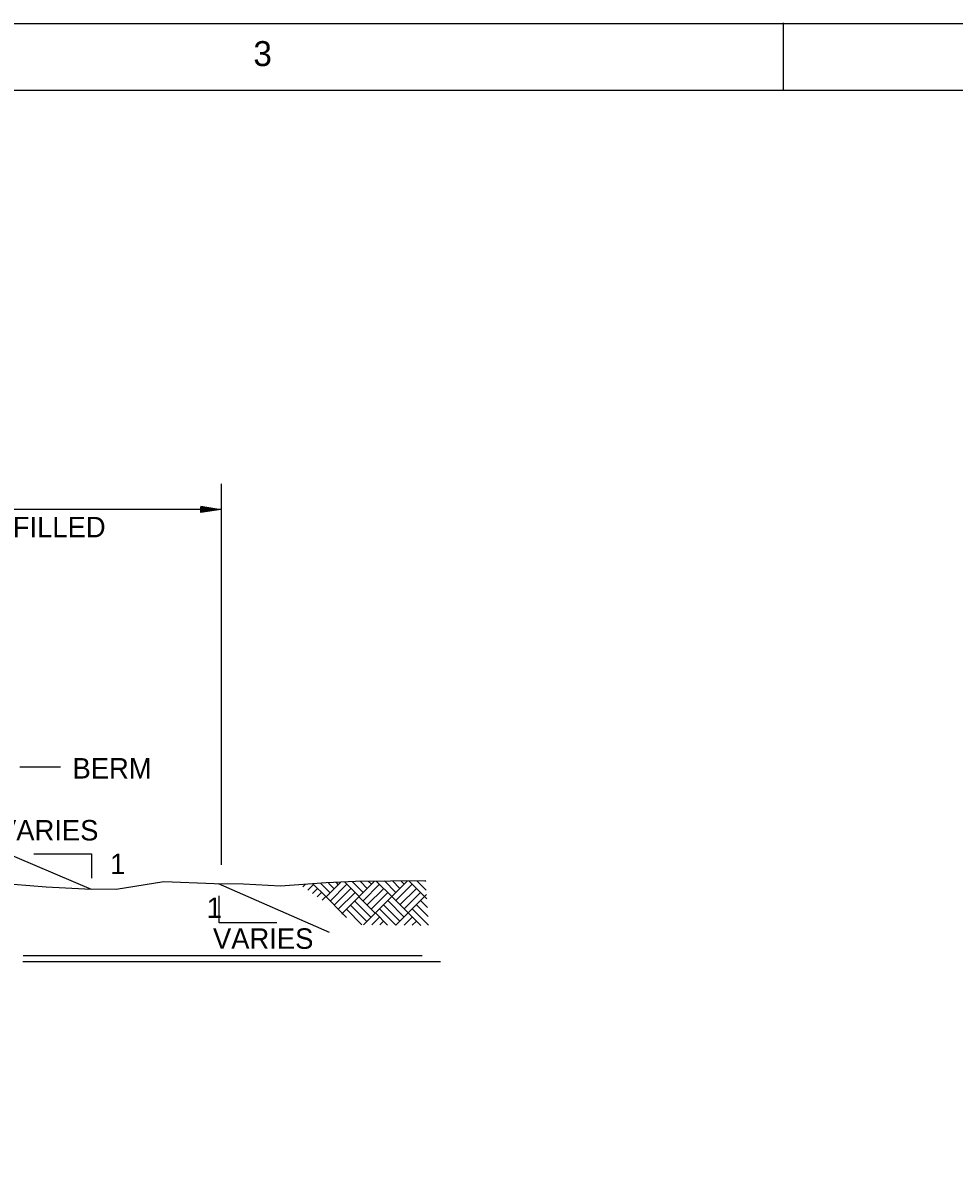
# Model space of a CAD drawing. Extents: x 2127959 to 2137375, y 2146193 to 2153470.
# Drawn here: x 2132094 to 2133592, y 2151626 to 2153470 of the extents above; entities that cross this region are included whole.
import ezdxf

# ---------------------------------------------------------------- set-up
doc = ezdxf.new("R2010")
doc.units = 0
for name, color, linetype in [('Level 1', 7, 'Continuous'), ('Level 3', 7, 'Continuous'), ('Level 5', 7, 'Continuous'), ('Level 50', 7, 'Continuous')]:
    doc.layers.add(name, color=color, linetype=linetype)

msp = doc.modelspace()

# ---------------------------------------------------------------- linework, layer by layer
at = {"layer": 'Level 1'}
for p, q in [((2133317.479, 2153362.032), (2133317.499, 2153469.881)), ((2128280.166, 2153362.032), (2136678.794, 2153362.027)), ((2132154.777, 2152273.049), (2132089.203, 2152273.049)), ((2132055.253, 2152140.601), (2132204.181, 2152077.145)), ((2132055.253, 2152140.601), (2132204.181, 2152077.145)), ((2132055.253, 2152140.601), (2132204.181, 2152077.145)), ((2132408.448, 2152086.019), (2132586.625, 2152008.043)), ((2132408.448, 2152086.019), (2132586.625, 2152008.043)), ((2132408.448, 2152086.019), (2132586.625, 2152008.043))]:
    msp.add_line(p, q, dxfattribs=at)
msp.add_lwpolyline([(2127959.193, 2153469.025), (2137374.681, 2153469.025), (2137374.681, 2146193.484), (2127959.193, 2146193.484)], close=True, dxfattribs=at)
at = {"layer": 'Level 3'}
for p, q in [((2132413.663, 2152116.49), (2132413.663, 2152728.641)), ((2132413.663, 2152687.675), (2131787.674, 2152687.675)), ((2132111.874, 2152134.155), (2132204.383, 2152134.155)), ((2132204.383, 2152134.155), (2132204.383, 2152094.984)), ((2132409.712, 2152023.008), (2132409.712, 2152066.457)), ((2132502.6, 2152023.008), (2132409.712, 2152023.008)), ((2132094.614, 2151970.318), (2132736.266, 2151970.318)), ((2132094.614, 2151970.318), (2132736.266, 2151970.318)), ((2132094.614, 2151970.318), (2132736.266, 2151970.318)), ((2132094.405, 2151961.01), (2132765.709, 2151961.01)), ((2132094.405, 2151961.01), (2132765.709, 2151961.01)), ((2132094.405, 2151961.01), (2132765.709, 2151961.01))]:
    msp.add_line(p, q, dxfattribs=at)
at = {"layer": 'Level 5'}
for p, q in [((2132079.302, 2152085.126), (2132131.876, 2152080.794)), ((2132079.302, 2152085.126), (2132131.876, 2152080.794)), ((2132079.302, 2152085.126), (2132131.876, 2152080.794)), ((2132131.876, 2152080.794), (2132193.754, 2152077.667)), ((2132131.876, 2152080.794), (2132193.754, 2152077.667)), ((2132131.876, 2152080.794), (2132193.754, 2152077.667)), ((2132244.523, 2152077.426), (2132321.132, 2152089.685)), ((2132244.523, 2152077.426), (2132321.132, 2152089.685)), ((2132244.523, 2152077.426), (2132321.132, 2152089.685)), ((2132321.132, 2152089.685), (2132401.941, 2152086.08)), ((2132321.132, 2152089.685), (2132401.941, 2152086.08)), ((2132321.132, 2152089.685), (2132401.941, 2152086.08)), ((2132401.941, 2152086.08), (2132449.091, 2152085.606)), ((2132401.941, 2152086.08), (2132449.091, 2152085.606)), ((2132401.941, 2152086.08), (2132449.091, 2152085.606)), ((2132449.091, 2152085.606), (2132508.573, 2152082.475)), ((2132449.091, 2152085.606), (2132508.573, 2152082.475)), ((2132449.091, 2152085.606), (2132508.573, 2152082.475)), ((2132508.573, 2152082.475), (2132581.873, 2152088.001)), ((2132508.573, 2152082.475), (2132581.873, 2152088.001)), ((2132508.573, 2152082.475), (2132581.873, 2152088.001)), ((2132548.708, 2152085.26), (2132544.628, 2152081.165)), ((2132552.34, 2152075.713), (2132561.548, 2152084.931)), ((2132581.338, 2152065.187), (2132560.683, 2152085.841)), ((2132587.905, 2152071.752), (2132573.208, 2152086.452)), ((2132605.182, 2152088.001), (2132581.86, 2152064.678)), ((2132581.873, 2152088.001), (2132629.337, 2152089.921)), ((2132581.873, 2152088.001), (2132629.337, 2152089.921)), ((2132581.873, 2152088.001), (2132629.337, 2152089.921)), ((2132585.807, 2152087.063), (2132594.489, 2152078.351)), ((2132588.428, 2152058.067), (2132614.774, 2152084.409)), ((2132598.345, 2152087.675), (2132601.07, 2152084.931)), ((2132611.931, 2152088.329), (2132635.042, 2152065.216)), ((2132641.654, 2152071.767), (2132624.467, 2152088.938)), ((2132629.337, 2152089.921), (2132741.988, 2152090.888)), ((2132629.337, 2152089.921), (2132741.988, 2152090.888)), ((2132629.337, 2152089.921), (2132741.988, 2152090.888)), ((2132660.059, 2152090.191), (2132635.087, 2152065.216)), ((2132648.207, 2152078.365), (2132637.035, 2152089.549)), ((2132641.654, 2152058.604), (2132667.999, 2152084.948)), ((2132649.667, 2152090.102), (2132654.821, 2152084.948)), ((2132662.726, 2152090.22), (2132687.732, 2152065.216)), ((2132694.212, 2152071.901), (2132675.803, 2152090.325)), ((2132687.612, 2152065.32), (2132712.946, 2152090.636)), ((2132700.794, 2152078.487), (2132688.834, 2152090.443)), ((2132694.181, 2152058.752), (2132720.538, 2152085.098)), ((2132701.911, 2152090.547), (2132707.39, 2152085.081)), ((2132740.271, 2152065.32), (2132714.912, 2152090.653)), ((2132743.026, 2152075.476), (2132727.75, 2152090.769)), ((2132740.825, 2152090.875), (2132742.074, 2152089.622)), ((2132193.754, 2152077.667), (2132244.523, 2152077.426)), ((2132193.754, 2152077.667), (2132244.523, 2152077.426)), ((2132193.754, 2152077.667), (2132244.523, 2152077.426)), ((2132560.057, 2152070.279), (2132568.127, 2152078.351)), ((2132574.727, 2152071.752), (2132567.786, 2152064.826)), ((2132581.293, 2152065.187), (2132575.485, 2152059.378)), ((2132608.19, 2152038.305), (2132581.86, 2152064.635)), ((2132595.024, 2152051.513), (2132621.355, 2152077.845)), ((2132627.951, 2152071.246), (2132601.594, 2152044.888)), ((2132634.504, 2152064.678), (2132608.19, 2152038.347)), ((2132634.504, 2152064.635), (2132660.731, 2152038.408)), ((2132648.251, 2152052.05), (2132674.567, 2152078.365)), ((2132681.166, 2152071.767), (2132654.821, 2152045.424)), ((2132661.296, 2152038.986), (2132687.628, 2152065.32)), ((2132713.944, 2152038.986), (2132687.612, 2152065.32)), ((2132727.109, 2152078.487), (2132700.777, 2152052.156)), ((2132733.706, 2152071.918), (2132707.36, 2152045.572)), ((2132713.944, 2152038.986), (2132740.271, 2152065.32)), ((2132743.506, 2152068.521), (2132740.168, 2152065.199)), ((2132740.271, 2152065.32), (2132743.967, 2152061.625)), ((2132639.643, 2152019.998), (2132614.774, 2152044.888)), ((2132647.564, 2152025.257), (2132621.355, 2152051.47)), ((2132627.951, 2152058.067), (2132654.164, 2152031.857)), ((2132694.077, 2152019.344), (2132667.837, 2152045.572)), ((2132674.463, 2152052.156), (2132700.777, 2152025.822)), ((2132681.015, 2152058.752), (2132707.36, 2152032.405)), ((2132746.841, 2152019.272), (2132720.538, 2152045.572)), ((2132745.888, 2152033.389), (2132727.109, 2152052.156)), ((2132733.706, 2152058.752), (2132744.936, 2152047.522)), ((2132608.19, 2152038.305), (2132607.013, 2152037.126)), ((2132608.19, 2152038.305), (2132614.998, 2152031.498)), ((2132642.295, 2152019.969), (2132660.731, 2152038.408)), ((2132655.267, 2152019.822), (2132667.314, 2152031.871)), ((2132680.777, 2152019.511), (2132661.296, 2152038.986)), ((2132673.883, 2152025.243), (2132668.282, 2152019.658)), ((2132694.33, 2152019.344), (2132713.944, 2152038.946)), ((2132707.316, 2152019.18), (2132720.538, 2152032.405)), ((2132713.944, 2152038.986), (2132734.064, 2152018.854)), ((2132727.109, 2152025.779), (2132720.361, 2152019.019))]:
    msp.add_line(p, q, dxfattribs=at)
at = {"layer": 'Level 50'}
for p, q in [((2132403.528, 2152687.752), (2132403.528, 2152687.752)), ((2132412.409, 2152687.685), (2132412.409, 2152687.685))]:
    msp.add_line(p, q, dxfattribs=at)
msp.add_lwpolyline([(2132380.504, 2152693.207), (2132412.409, 2152687.685), (2132380.439, 2152682.617), (2132380.503, 2152691.666), (2132403.528, 2152687.752), (2132381.823, 2152684.316), (2132381.853, 2152690.13), (2132394.994, 2152687.818), (2132383.202, 2152686.015), (2132383.212, 2152688.401), (2132386.108, 2152687.876)], dxfattribs=at)

# ---------------------------------------------------------------- texts
at = {"layer": 'Level 1'}
for s, height, p in [('3', 40.073, (2132464.975, 2153400.552)), ('EXCAVATION IN THIS AREA TO BE BACKFILLED', 32.931, (2131216.694, 2152642.858)), ('BERM', 32.931, (2132174.055, 2152255.048)), ('VARIES', 32.931, (2132054.238, 2152155.441)), ('1', 32.931, (2132234.555, 2152101.424)), ('1', 32.931, (2132389.762, 2152030.787)), ('VARIES', 32.931, (2132399.99, 2151981.257))]:
    msp.add_text(s, height=height, dxfattribs=at).set_placement(p)

doc.saveas('drawing.dxf')
